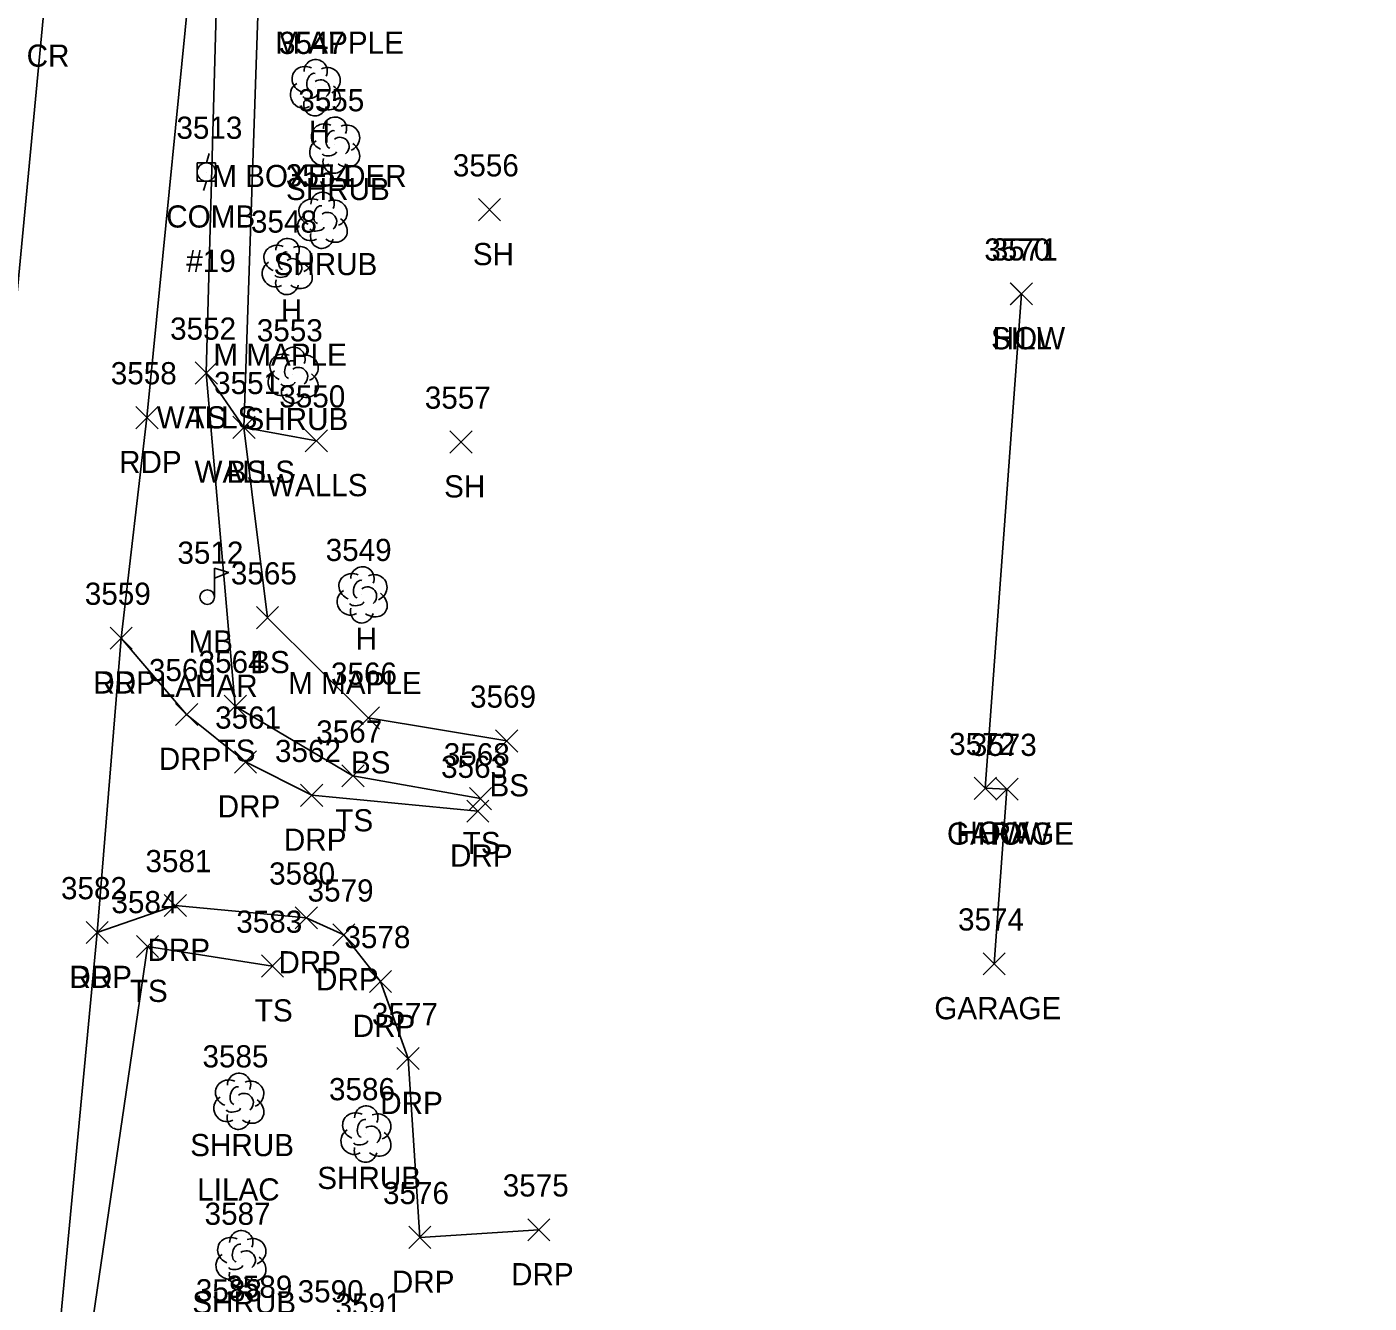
# Model space of a CAD drawing. Extents: x 1678863 to 1683592, y 407783 to 418211.
# Drawn here: x 1680374.7 to 1680495.8, y 414490.1 to 414605.2 of the extents above; entities that cross this region are included whole.
import ezdxf

# ---------------------------------------------------------------- set-up
doc = ezdxf.new("R2010")
doc.units = 0
for name, color, linetype in [('L_A', 7, 'Continuous'), ('L_C', 7, 'Continuous'), ('L_I', 7, 'Continuous'), ('L_TIC', 7, 'Continuous'), ('LBC', 7, 'Continuous'), ('LELB', 7, 'Continuous'), ('LMB', 7, 'Continuous'), ('LSH', 7, 'Continuous'), ('LTD', 7, 'Continuous'), ('LWS', 7, 'Continuous'), ('P_A', 7, 'Continuous'), ('P_I', 7, 'Continuous'), ('P_TIC', 7, 'Continuous'), ('PET', 7, 'Continuous'), ('PRC', 7, 'Continuous'), ('R_A', 7, 'Continuous'), ('R_I', 7, 'Continuous'), ('R_TIC', 7, 'Continuous'), ('RDP', 7, 'Continuous'), ('U_A', 7, 'Continuous'), ('U_C', 7, 'Continuous'), ('U_I', 7, 'Continuous'), ('UP', 7, 'Continuous')]:
    doc.layers.add(name, color=color, linetype=linetype)

msp = doc.modelspace()

# ---------------------------------------------------------------- linework, layer by layer
at = {"layer": 'L_TIC'}
for points in [[(1680415.47, 414587.68), (1680417.47, 414589.68)], [(1680417.47, 414587.68), (1680415.47, 414589.68)], [(1680463.43, 414580.09), (1680465.43, 414582.09)], [(1680465.43, 414580.09), (1680463.43, 414582.09)], [(1680463.45, 414580.1), (1680465.45, 414582.1)], [(1680465.45, 414580.1), (1680463.45, 414582.1)], [(1680389.92, 414572.96), (1680391.92, 414574.96)], [(1680391.92, 414572.96), (1680389.92, 414574.96)], [(1680389.92, 414572.96), (1680391.92, 414574.96)], [(1680391.92, 414572.96), (1680389.92, 414574.96)], [(1680393.32, 414568.06), (1680395.32, 414570.06)], [(1680395.32, 414568.06), (1680393.32, 414570.06)], [(1680393.32, 414568.06), (1680395.32, 414570.06)], [(1680395.32, 414568.06), (1680393.32, 414570.06)], [(1680399.85, 414566.85), (1680401.85, 414568.85)], [(1680401.85, 414566.85), (1680399.85, 414568.85)], [(1680412.89, 414566.74), (1680414.89, 414568.74)], [(1680414.89, 414566.74), (1680412.89, 414568.74)], [(1680395.45, 414550.9), (1680397.45, 414552.9)], [(1680397.45, 414550.9), (1680395.45, 414552.9)], [(1680392.54, 414542.92), (1680394.54, 414544.92)], [(1680394.54, 414542.92), (1680392.54, 414544.92)], [(1680404.53, 414541.86), (1680406.53, 414543.86)], [(1680406.53, 414541.86), (1680404.53, 414543.86)], [(1680417.02, 414539.79), (1680419.02, 414541.79)], [(1680419.02, 414539.79), (1680417.02, 414541.79)], [(1680403.15, 414536.64), (1680405.15, 414538.64)], [(1680405.15, 414536.64), (1680403.15, 414538.64)], [(1680414.65, 414534.59), (1680416.65, 414536.59)], [(1680416.65, 414534.59), (1680414.65, 414536.59)], [(1680460.18, 414535.52), (1680462.18, 414537.52)], [(1680462.18, 414535.52), (1680460.18, 414537.52)], [(1680462.13, 414535.44), (1680464.13, 414537.44)], [(1680464.13, 414535.44), (1680462.13, 414537.44)], [(1680462.13, 414535.44), (1680464.13, 414537.44)], [(1680464.13, 414535.44), (1680462.13, 414537.44)], [(1680384.62, 414521.26), (1680386.62, 414523.26)], [(1680386.62, 414521.26), (1680384.62, 414523.26)], [(1680395.89, 414519.5), (1680397.89, 414521.5)], [(1680397.89, 414519.5), (1680395.89, 414521.5)], [(1680460.98, 414519.7), (1680462.98, 414521.7)], [(1680462.98, 414519.7), (1680460.98, 414521.7)]]:
    msp.add_lwpolyline(points, dxfattribs=at)
at = {"layer": 'LBC'}
for points in [[(1680464.45, 414581.1), (1680461.18, 414536.52), (1680463.13, 414536.44)], [(1680463.13, 414536.44), (1680461.98, 414520.7)]]:
    msp.add_lwpolyline(points, dxfattribs=at)
at = {"layer": 'LELB'}
for points in [[(1680395.79, 414677.26), (1680395.48, 414652.23), (1680392.09, 414616.25), (1680390.92, 414573.96), (1680393.54, 414543.92), (1680404.15, 414537.64), (1680415.65, 414535.59)], [(1680397.23, 414641.55), (1680395.9, 414615.92), (1680394.32, 414569.06), (1680396.45, 414551.9), (1680405.53, 414542.86), (1680418.02, 414540.79)], [(1680396.89, 414520.5), (1680385.62, 414522.26), (1680380.04, 414484.11), (1680378.3, 414453.59), (1680382.06, 414440.91), (1680386.06, 414431.85), (1680391.41, 414432.41), (1680406.16, 414439.4)]]:
    msp.add_lwpolyline(points, dxfattribs=at)
at = {"layer": 'LMB'}
for p, q in [((1680391.66, 414556.36), (1680392.96, 414555.98)), ((1680391.67, 414553.77), (1680391.67, 414556.36)), ((1680391.67, 414555.46), (1680392.95, 414555.97)), ((1680391.01, 414553.76), (1680391.01, 414553.76))]:
    msp.add_line(p, q, dxfattribs=at)
msp.add_circle((1680391.01, 414553.76), 0.656, dxfattribs=at)
at = {"layer": 'LSH'}
for p, q in [((1680402.48, 414594.55), (1680402.48, 414594.55)), ((1680402.48, 414594.55), (1680402.48, 414594.55)), ((1680401.36, 414587.78), (1680401.36, 414587.78)), ((1680401.36, 414587.78), (1680401.36, 414587.78)), ((1680398.74, 414573.81), (1680398.74, 414573.81)), ((1680398.74, 414573.81), (1680398.74, 414573.81)), ((1680393.84, 414508.36), (1680393.84, 414508.36)), ((1680393.84, 414508.36), (1680393.84, 414508.36)), ((1680405.3, 414505.4), (1680405.3, 414505.4)), ((1680405.3, 414505.4), (1680405.3, 414505.4)), ((1680394.03, 414494.17), (1680394.03, 414494.17)), ((1680394.03, 414494.17), (1680394.03, 414494.17))]:
    msp.add_line(p, q, dxfattribs=at)
for centre in [(1680402.53, 414595.98), (1680401.41, 414589.21), (1680398.79, 414575.24), (1680393.88, 414509.79), (1680405.35, 414506.84), (1680394.08, 414495.6)]:
    msp.add_arc(centre, 1.05, 335.5272, 180.9563, dxfattribs=at)
for centre, major_axis, ratio, start_param, end_param in [((1680401.69, 414595.22), (1.21, -0.51), 0.895232, 1.570796, 4.712389), ((1680402.28, 414595.01), (-0.208, -0.792), 0.645439, 3.141593, 6.283185), ((1680403.53, 414595.13), (-1.14, -0.48), 0.949671, 1.570796, 4.712389), ((1680401.4, 414593.84), (0.58, -1.04), 0.959034, 3.141593, 6.283185), ((1680402.98, 414594.38), (-0.5, 0.667), 0.989748, 3.141593, 6.283185), ((1680403.48, 414593.72), (-1.09, 0.79), 0.841452, 1.570796, 4.712389), ((1680402.03, 414593.8), (-0.625, -0.083), 0.423636, 0, 3.141593), ((1680402.48, 414593.05), (0.26, 1.06), 0.942809, 1.570796, 4.712389), ((1680400.57, 414588.45), (1.21, -0.51), 0.895232, 1.570796, 4.712389), ((1680401.15, 414588.24), (-0.208, -0.792), 0.645439, 3.141593, 6.283185), ((1680401.86, 414587.61), (-0.5, 0.667), 0.989748, 3.141593, 6.283185), ((1680402.4, 414588.36), (-1.14, -0.48), 0.949671, 1.570796, 4.712389), ((1680400.28, 414587.07), (0.58, -1.04), 0.959034, 3.141593, 6.283185), ((1680402.36, 414586.95), (-1.09, 0.79), 0.841452, 1.570796, 4.712389), ((1680401.36, 414586.28), (0.26, 1.06), 0.942809, 1.570796, 4.712389), ((1680400.91, 414587.03), (-0.625, -0.083), 0.423636, 0, 3.141593), ((1680397.95, 414574.47), (1.21, -0.51), 0.895232, 1.570796, 4.712389), ((1680399.79, 414574.39), (-1.14, -0.48), 0.949671, 1.570796, 4.712389), ((1680397.66, 414573.1), (0.58, -1.04), 0.959034, 3.141593, 6.283185), ((1680398.54, 414574.26), (-0.208, -0.792), 0.645439, 3.141593, 6.283185), ((1680399.24, 414573.64), (-0.5, 0.667), 0.989748, 3.141593, 6.283185), ((1680398.29, 414573.06), (-0.625, -0.083), 0.423636, 0, 3.141593), ((1680399.74, 414572.97), (-1.09, 0.79), 0.841452, 1.570796, 4.712389), ((1680398.74, 414572.31), (0.26, 1.06), 0.942809, 1.570796, 4.712389), ((1680393.04, 414509.03), (1.21, -0.51), 0.895232, 1.570796, 4.712389), ((1680394.88, 414508.94), (-1.14, -0.48), 0.949671, 1.570796, 4.712389), ((1680392.75, 414507.65), (0.58, -1.04), 0.959034, 3.141593, 6.283185), ((1680393.63, 414508.82), (-0.208, -0.792), 0.645439, 3.141593, 6.283185), ((1680394.34, 414508.19), (-0.5, 0.667), 0.989748, 3.141593, 6.283185), ((1680393.38, 414507.61), (-0.625, -0.083), 0.423636, 0, 3.141593), ((1680394.84, 414507.53), (-1.09, 0.79), 0.841452, 1.570796, 4.712389), ((1680404.51, 414506.07), (1.21, -0.51), 0.895232, 1.570796, 4.712389), ((1680393.84, 414506.86), (0.26, 1.06), 0.942809, 1.570796, 4.712389), ((1680405.09, 414505.86), (-0.208, -0.792), 0.645439, 3.141593, 6.283185), ((1680406.34, 414505.99), (-1.14, -0.48), 0.949671, 1.570796, 4.712389), ((1680404.22, 414504.69), (0.58, -1.04), 0.959034, 3.141593, 6.283185), ((1680405.8, 414505.24), (-0.5, 0.667), 0.989748, 3.141593, 6.283185), ((1680406.3, 414504.57), (-1.09, 0.79), 0.841452, 1.570796, 4.712389), ((1680405.3, 414503.9), (0.26, 1.06), 0.942809, 1.570796, 4.712389), ((1680404.84, 414504.65), (-0.625, -0.083), 0.423636, 0, 3.141593), ((1680393.24, 414494.83), (1.21, -0.51), 0.895232, 1.570796, 4.712389), ((1680393.82, 414494.62), (-0.208, -0.792), 0.645439, 3.141593, 6.283185), ((1680395.07, 414494.75), (-1.14, -0.48), 0.949671, 1.570796, 4.712389), ((1680392.95, 414493.46), (0.58, -1.04), 0.959034, 3.141593, 6.283185), ((1680394.53, 414494), (-0.5, 0.667), 0.989748, 3.141593, 6.283185), ((1680395.03, 414493.33), (-1.09, 0.79), 0.841452, 1.570796, 4.712389), ((1680394.03, 414492.67), (0.26, 1.06), 0.942809, 1.570796, 4.712389), ((1680393.57, 414493.42), (-0.625, -0.083), 0.423636, 0, 3.141593)]:
    msp.add_ellipse(centre, major_axis=major_axis, ratio=ratio, start_param=start_param, end_param=end_param, dxfattribs=at)
at = {"layer": 'LTD'}
for p, q in [((1680400.74, 414599.72), (1680400.74, 414599.72)), ((1680400.74, 414599.72), (1680400.74, 414599.72)), ((1680398.21, 414583.61), (1680398.21, 414583.61)), ((1680398.21, 414583.61), (1680398.21, 414583.61)), ((1680404.96, 414554.01), (1680404.96, 414554.01)), ((1680404.96, 414554.01), (1680404.96, 414554.01))]:
    msp.add_line(p, q, dxfattribs=at)
for centre in [(1680400.79, 414601.16), (1680398.25, 414585.04), (1680405.01, 414555.45)]:
    msp.add_arc(centre, 1.05, 335.5272, 180.9563, dxfattribs=at)
for centre, major_axis, ratio, start_param, end_param in [((1680399.95, 414600.39), (1.21, -0.51), 0.895232, 1.570796, 4.712389), ((1680400.53, 414600.18), (-0.208, -0.792), 0.645439, 3.141593, 6.283185), ((1680401.78, 414600.31), (-1.14, -0.48), 0.949671, 1.570796, 4.712389), ((1680399.66, 414599.01), (0.58, -1.04), 0.959034, 3.141593, 6.283185), ((1680401.24, 414599.56), (-0.5, 0.667), 0.989748, 3.141593, 6.283185), ((1680401.74, 414598.89), (-1.09, 0.79), 0.841452, 1.570796, 4.712389), ((1680400.74, 414598.22), (0.26, 1.06), 0.942809, 1.570796, 4.712389), ((1680400.28, 414598.97), (-0.625, -0.083), 0.423636, 0, 3.141593), ((1680397.41, 414584.28), (1.21, -0.51), 0.895232, 1.570796, 4.712389), ((1680398, 414584.07), (-0.208, -0.792), 0.645439, 3.141593, 6.283185), ((1680399.25, 414584.19), (-1.14, -0.48), 0.949671, 1.570796, 4.712389), ((1680397.12, 414582.9), (0.58, -1.04), 0.959034, 3.141593, 6.283185), ((1680398.71, 414583.44), (-0.5, 0.667), 0.989748, 3.141593, 6.283185), ((1680397.75, 414582.86), (-0.625, -0.083), 0.423636, 0, 3.141593), ((1680399.21, 414582.78), (-1.09, 0.79), 0.841452, 1.570796, 4.712389), ((1680398.21, 414582.11), (0.26, 1.06), 0.942809, 1.570796, 4.712389), ((1680404.17, 414554.68), (1.21, -0.51), 0.895232, 1.570796, 4.712389), ((1680406, 414554.6), (-1.14, -0.48), 0.949671, 1.570796, 4.712389), ((1680404.75, 414554.47), (-0.208, -0.792), 0.645439, 3.141593, 6.283185), ((1680405.46, 414553.85), (-0.5, 0.667), 0.989748, 3.141593, 6.283185), ((1680403.88, 414553.31), (0.58, -1.04), 0.959034, 3.141593, 6.283185), ((1680405.96, 414553.18), (-1.09, 0.79), 0.841452, 1.570796, 4.712389), ((1680404.96, 414552.51), (0.26, 1.06), 0.942809, 1.570796, 4.712389), ((1680404.5, 414553.26), (-0.625, -0.083), 0.423636, 0, 3.141593)]:
    msp.add_ellipse(centre, major_axis=major_axis, ratio=ratio, start_param=start_param, end_param=end_param, dxfattribs=at)
at = {"layer": 'LWS'}
msp.add_lwpolyline([(1680400.85, 414567.85), (1680394.32, 414569.06), (1680390.92, 414573.96)], dxfattribs=at)
at = {"layer": 'P_TIC'}
for points in [[(1680384.57, 414568.94), (1680386.57, 414570.94)], [(1680386.57, 414568.94), (1680384.57, 414570.94)], [(1680382.24, 414549.06), (1680384.24, 414551.06)], [(1680384.24, 414549.06), (1680382.24, 414551.06)], [(1680380.08, 414522.52), (1680382.08, 414524.52)], [(1680382.08, 414522.52), (1680380.08, 414524.52)]]:
    msp.add_lwpolyline(points, dxfattribs=at)
at = {"layer": 'PET'}
msp.add_lwpolyline([(1680495.8, 415211.55), (1680487.74, 415180.8), (1680478.66, 415148.16), (1680471.94, 415120.07), (1680462.57, 415079.59), (1680454.69, 415044.69), (1680445.65, 415004.54), (1680436.54, 414962.49), (1680430.18, 414933.71), (1680423.61, 414897.47), (1680418.44, 414869.8), (1680415.44, 414847.01), (1680410.82, 414817.35), (1680406.85, 414787.83), (1680404.02, 414758.7), (1680400.52, 414722.33), (1680395.79, 414677.26), (1680393.31, 414652.78), (1680390.17, 414616.43), (1680385.57, 414569.94), (1680383.24, 414550.06), (1680381.08, 414523.52), (1680377.37, 414484.42)], dxfattribs=at)
at = {"layer": 'PRC'}
msp.add_lwpolyline([(1680481.59, 415211.17), (1680473.06, 415178.67), (1680464.71, 415146.4), (1680454.43, 415103.39), (1680442.46, 415051.38), (1680433.87, 415013.05), (1680427.71, 414986.46), (1680420.88, 414953.3), (1680415, 414925.91), (1680408.48, 414889.99), (1680403.43, 414856.87), (1680399.05, 414826.29), (1680394.79, 414790.7), (1680390.07, 414747.8), (1680385.23, 414697.92), (1680381.06, 414656.38), (1680376.28, 414606.57), (1680371.5, 414556.43), (1680367.38, 414511.69), (1680362.63, 414458.59)], dxfattribs=at)
at = {"layer": 'R_TIC'}
for points in [[(1680382.24, 414549.06), (1680384.24, 414551.06)], [(1680384.24, 414549.06), (1680382.24, 414551.06)], [(1680388.15, 414542.18), (1680390.15, 414544.18)], [(1680390.15, 414542.18), (1680388.15, 414544.18)], [(1680393.46, 414537.9), (1680395.46, 414539.9)], [(1680395.46, 414537.9), (1680393.46, 414539.9)], [(1680399.43, 414534.89), (1680401.43, 414536.89)], [(1680401.43, 414534.89), (1680399.43, 414536.89)], [(1680414.41, 414533.46), (1680416.41, 414535.46)], [(1680416.41, 414533.46), (1680414.41, 414535.46)], [(1680387.13, 414524.96), (1680389.13, 414526.96)], [(1680389.13, 414524.96), (1680387.13, 414526.96)], [(1680398.94, 414523.84), (1680400.94, 414525.84)], [(1680400.94, 414523.84), (1680398.94, 414525.84)], [(1680380.08, 414522.52), (1680382.08, 414524.52)], [(1680382.08, 414522.52), (1680380.08, 414524.52)], [(1680402.33, 414522.31), (1680404.33, 414524.31)], [(1680404.33, 414522.31), (1680402.33, 414524.31)], [(1680405.64, 414518.11), (1680407.64, 414520.11)], [(1680407.64, 414518.11), (1680405.64, 414520.11)], [(1680408.12, 414511.16), (1680410.12, 414513.16)], [(1680410.12, 414511.16), (1680408.12, 414513.16)], [(1680409.18, 414495.04), (1680411.18, 414497.04)], [(1680411.18, 414495.04), (1680409.18, 414497.04)], [(1680419.92, 414495.72), (1680421.92, 414497.72)], [(1680421.92, 414495.72), (1680419.92, 414497.72)]]:
    msp.add_lwpolyline(points, dxfattribs=at)
at = {"layer": 'RDP'}
for points in [[(1680383.24, 414550.06), (1680389.15, 414543.18), (1680394.46, 414538.9), (1680400.43, 414535.89), (1680415.41, 414534.46)], [(1680420.92, 414496.72), (1680410.18, 414496.04), (1680409.12, 414512.16), (1680406.64, 414519.11), (1680403.33, 414523.31), (1680399.94, 414524.84), (1680388.13, 414525.96), (1680381.08, 414523.52)]]:
    msp.add_lwpolyline(points, dxfattribs=at)
at = {"layer": 'UP'}
for p, q in [((1680391.18, 414593.74), (1680390.93, 414592.9)), ((1680390.09, 414591.24), (1680390.09, 414592.9)), ((1680390.09, 414592.9), (1680391.76, 414592.9)), ((1680391.76, 414592.9), (1680391.76, 414591.24)), ((1680391.76, 414591.24), (1680390.09, 414591.24)), ((1680390.68, 414590.4), (1680390.93, 414591.24)), ((1680390.93, 414592.07), (1680390.93, 414592.07))]:
    msp.add_line(p, q, dxfattribs=at)
msp.add_circle((1680390.93, 414592.07), 0.833, dxfattribs=at)

# ---------------------------------------------------------------- texts
at = {"layer": 'L_A'}
for s, p in [('H', (1680400.17, 414594.72)), ('SHRUB', (1680398.11, 414589.55)), ('SH', (1680414.96, 414583.68)), ('SHRUB', (1680396.99, 414582.78)), ('H', (1680397.64, 414578.61)), ('SILL', (1680461.69, 414576.09)), ('HOW', (1680461.84, 414576.1)), ('WALLS', (1680386.46, 414568.96)), ('TS', (1680389.32, 414568.96)), ('SHRUB', (1680394.37, 414568.81)), ('WALLS', (1680389.86, 414564.06)), ('BS', (1680392.76, 414564.06)), ('WALLS', (1680396.4, 414562.85)), ('SH', (1680412.37, 414562.74)), ('H', (1680404.39, 414549.01)), ('MB', (1680389.32, 414548.76)), ('BS', (1680394.89, 414546.9)), ('TS', (1680391.95, 414538.92)), ('BS', (1680403.97, 414537.86)), ('BS', (1680416.46, 414535.79)), ('TS', (1680402.56, 414532.64)), ('GARAGE', (1680457.72, 414531.44)), ('HOW', (1680458.57, 414531.52)), ('HOW', (1680460.51, 414531.44)), ('TS', (1680414.05, 414530.59)), ('TS', (1680384.03, 414517.26)), ('TS', (1680395.3, 414515.5)), ('GARAGE', (1680456.58, 414515.7)), ('SHRUB', (1680389.47, 414503.36)), ('SHRUB', (1680400.93, 414500.4)), ('SHRUB', (1680389.66, 414489.17))]:
    msp.add_text(s, height=2, dxfattribs=at).set_placement(p)
at = {"layer": 'L_C'}
for s, p in [('M APPLE', (1680397.15, 414602.74)), ('M BOXELDER', (1680391.46, 414590.72)), ('M MAPLE', (1680391.56, 414574.61)), ('LAHAR', (1680386.64, 414544.76)), ('M MAPLE', (1680398.31, 414545.01)), ('LILAC', (1680390.11, 414499.36))]:
    msp.add_text(s, height=2, dxfattribs=at).set_placement(p)
at = {"layer": 'L_I'}
for s, p in [('3547', (1680397.48, 414602.72)), ('3555', (1680399.22, 414597.55)), ('3556', (1680413.16, 414591.68)), ('3554', (1680398.1, 414590.78)), ('3548', (1680394.95, 414586.61)), ('3571', (1680461.76, 414584.1)), ('3570', (1680461.09, 414584.09)), ('3552', (1680387.66, 414576.96)), ('3552', (1680387.66, 414576.96)), ('3553', (1680395.48, 414576.81)), ('3551', (1680391.63, 414572.06)), ('3551', (1680391.63, 414572.06)), ('3550', (1680397.51, 414570.85)), ('3557', (1680410.63, 414570.74)), ('3512', (1680388.32, 414556.76)), ('3549', (1680401.69, 414557.01)), ('3565', (1680393.14, 414554.9)), ('3564', (1680390.23, 414546.92)), ('3566', (1680402.17, 414545.86)), ('3569', (1680414.71, 414543.79)), ('3567', (1680400.84, 414540.64)), ('3572', (1680457.92, 414539.52)), ('3573', (1680459.87, 414539.44)), ('3573', (1680459.87, 414539.44)), ('3568', (1680412.34, 414538.59)), ('3584', (1680382.37, 414525.26)), ('3574', (1680458.72, 414523.7)), ('3583', (1680393.63, 414523.5)), ('3585', (1680390.58, 414511.36)), ('3586', (1680401.99, 414508.4)), ('3587', (1680390.77, 414497.17)), ('3588', (1680389.98, 414490.27)), ('3589', (1680392.73, 414490.59)), ('3590', (1680399.16, 414490.18)), ('3591', (1680402.58, 414488.99))]:
    msp.add_text(s, height=2, dxfattribs=at).set_placement(p)
at = {"layer": 'P_A'}
for s, p in [('CR', (1680374.72, 414601.57)), ('RDP', (1680383.06, 414564.94)), ('RDP', (1680380.73, 414545.06)), ('RDP', (1680378.57, 414518.52))]:
    msp.add_text(s, height=2, dxfattribs=at).set_placement(p)
at = {"layer": 'P_I'}
for s, p in [('3558', (1680382.31, 414572.94)), ('3559', (1680379.97, 414553.06)), ('3582', (1680377.82, 414526.52))]:
    msp.add_text(s, height=2, dxfattribs=at).set_placement(p)
at = {"layer": 'R_A'}
for p in [(1680380.73, 414545.06), (1680386.64, 414538.18), (1680391.95, 414533.9), (1680397.92, 414530.89), (1680412.9, 414529.46), (1680385.62, 414520.96), (1680397.43, 414519.84), (1680378.57, 414518.52), (1680400.82, 414518.31), (1680404.13, 414514.11), (1680406.61, 414507.16), (1680407.66, 414491.04), (1680418.41, 414491.72)]:
    msp.add_text('DRP', height=2, dxfattribs=at).set_placement(p)
at = {"layer": 'R_I'}
for s, p in [('3559', (1680379.97, 414553.06)), ('3560', (1680385.75, 414546.18)), ('3561', (1680391.72, 414541.9)), ('3562', (1680397.12, 414538.89)), ('3563', (1680412.1, 414537.46)), ('3581', (1680385.44, 414528.96)), ('3580', (1680396.59, 414527.84)), ('3582', (1680377.82, 414526.52)), ('3579', (1680400.06, 414526.31)), ('3578', (1680403.38, 414522.11)), ('3577', (1680405.86, 414515.16)), ('3575', (1680417.66, 414499.72)), ('3576', (1680406.86, 414499.04))]:
    msp.add_text(s, height=2, dxfattribs=at).set_placement(p)
at = {"layer": 'U_A'}
msp.add_text('COMB', height=2, dxfattribs=at).set_placement((1680387.31, 414587.07))
at = {"layer": 'U_C'}
msp.add_text('#19', height=2, dxfattribs=at).set_placement((1680389.12, 414583.07))
at = {"layer": 'U_I'}
msp.add_text('3513', height=2, dxfattribs=at).set_placement((1680388.23, 414595.07))

doc.saveas('drawing.dxf')
